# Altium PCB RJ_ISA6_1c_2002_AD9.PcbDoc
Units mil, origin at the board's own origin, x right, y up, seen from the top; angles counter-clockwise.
Board outline 1897.64 x 578.74 mil, 2 copper layers (TOP, Bottom); 8 components, 8 nets, 22 pads, 1 vias.
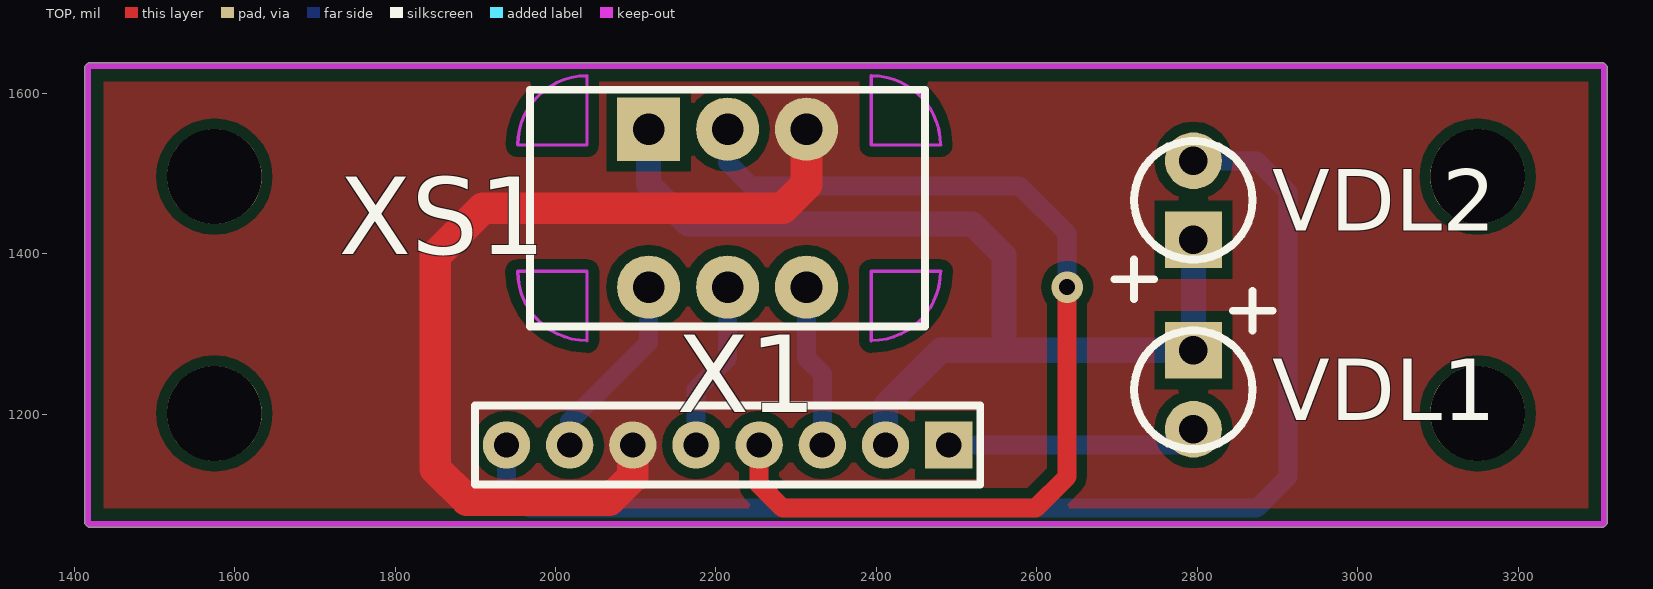
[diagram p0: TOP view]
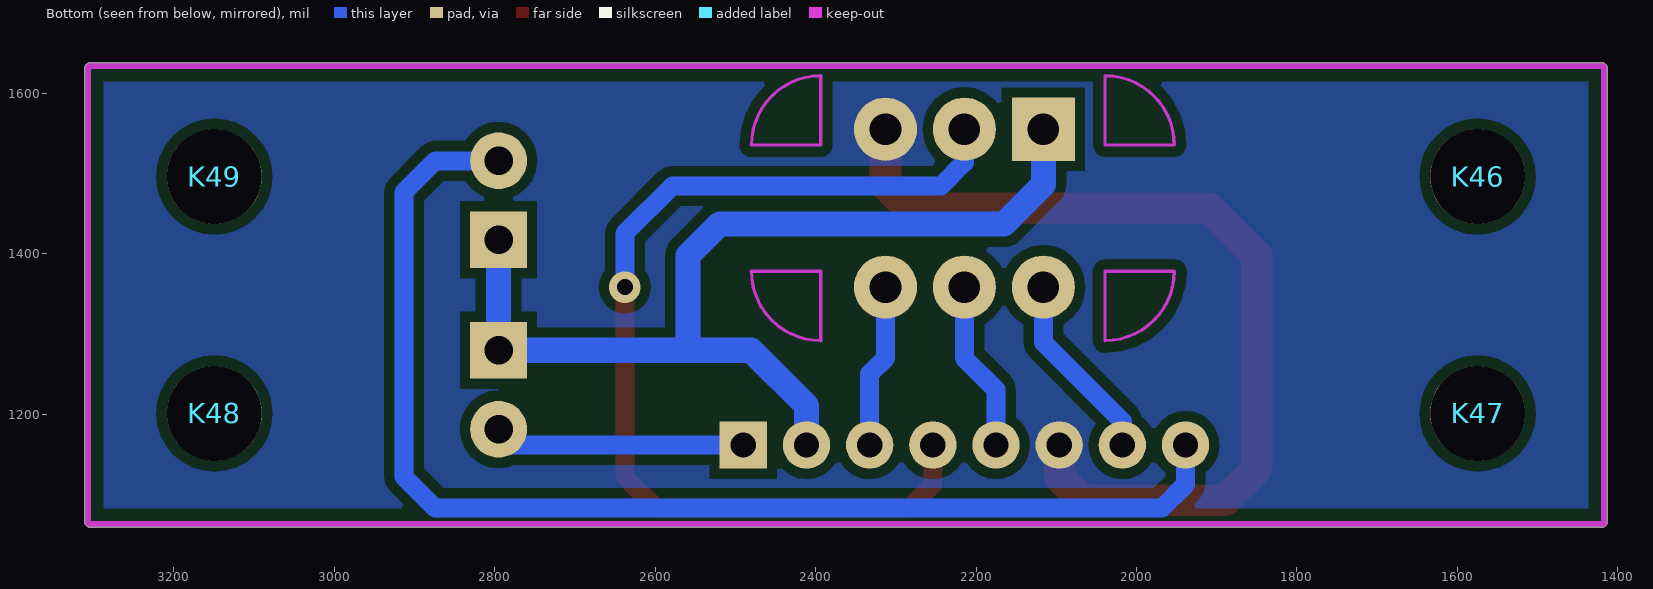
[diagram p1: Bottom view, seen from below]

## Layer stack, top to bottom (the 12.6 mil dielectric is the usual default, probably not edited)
TOP: signal copper 1.4
Dielectric: dielectric 12.6, FR-4, Dk 4.8
Bottom: signal copper 1.4

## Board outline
1413.39,1062.99 1417.32,1059.06 3307.09,1059.06 3311.02,1062.99 3311.02,1633.86 3307.09,1637.8 1417.32,1637.8 1413.39,1633.86

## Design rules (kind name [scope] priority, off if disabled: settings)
Clearance Clearance_TOP_PadToPad [ExistsOnLayer('TOP') And IsPad vs ExistsOnLayer('TOP') And IsPad] p1: gap=15.75
Clearance Clearance_TOP_PadToLine [ExistsOnLayer('TOP') And IsPad vs ExistsOnLayer('TOP') And IsWire] p2: gap=13
Clearance Clearance_TOP_LineToLine [ExistsOnLayer('TOP') And IsWire vs ExistsOnLayer('TOP') And IsWire] p3: gap=13
Clearance Clearance_TOP_ViaToPad [ExistsOnLayer('TOP') And IsVia vs ExistsOnLayer('TOP') And IsPad] p4: gap=15.75
Clearance Clearance_TOP_ViaToLine [ExistsOnLayer('TOP') And IsVia vs ExistsOnLayer('TOP') And IsWire] p5: gap=13
Clearance Clearance_TOP_ViaToVia [ExistsOnLayer('TOP') And IsVia vs ExistsOnLayer('TOP') And IsVia] p6: gap=15.75
Clearance Clearance_Bottom_PadToPad [ExistsOnLayer('Bottom') And IsPad vs ExistsOnLayer('Bottom') And IsPad] p7: gap=15.75
Clearance Clearance_Bottom_PadToLine [ExistsOnLayer('Bottom') And IsPad vs ExistsOnLayer('Bottom') And IsWire] p8: gap=13
Clearance Clearance_Bottom_LineToLine [ExistsOnLayer('Bottom') And IsWire vs ExistsOnLayer('Bottom') And IsWire] p9: gap=13
Clearance Clearance_Bottom_ViaToPad [ExistsOnLayer('Bottom') And IsVia vs ExistsOnLayer('Bottom') And IsPad] p10: gap=15.75
Clearance Clearance_Bottom_ViaToLine [ExistsOnLayer('Bottom') And IsVia vs ExistsOnLayer('Bottom') And IsWire] p11: gap=13
Clearance Clearance_Bottom_ViaToVia [ExistsOnLayer('Bottom') And IsVia vs ExistsOnLayer('Bottom') And IsVia] p12: gap=15.75
Clearance [All] p13: gap=13
PlaneClearance [All] p1: clearance=10
PolygonConnect PolygonConnect_4 [IsPolygon And InNet('GND') And OnLayer('Bottom') vs IsVia] p1: connectstyle=Direct reliefconductorwidth=0 reliefentries=4 polygonreliefangle="90 Angle"
PolygonConnect PolygonConnect_3 [IsPolygon And InNet('GND') And OnLayer('Bottom') vs IsPad] p2: connectstyle=Direct reliefconductorwidth=0 reliefentries=4 polygonreliefangle="90 Angle"
PolygonConnect PolygonConnect_2 [IsPolygon And InNet('GND') And OnLayer('TOP') vs IsVia] p3: connectstyle=Direct reliefconductorwidth=0 reliefentries=4 polygonreliefangle="90 Angle"
PolygonConnect PolygonConnect_1 [IsPolygon And InNet('GND') And OnLayer('TOP') vs IsPad] p4: connectstyle=Direct reliefconductorwidth=0 reliefentries=4 polygonreliefangle="90 Angle"
PolygonConnect [All] p5: connectstyle=Relief reliefconductorwidth=10 reliefentries=4 polygonreliefangle="90 Angle"
RoutingVias [All] p1: holewidth=28 width=50 viastyle="Through Hole" minholewidth=28 minwidth=50 maxholewidth=28 maxwidth=50
SilkscreenOverComponentPads [All] p1: minsilkscreentomaskgap=10
SolderMaskExpansion [All] p1: expansion=4
TestPointUsage [All] p1: valid=0 allowmultiple=FALSE
Testpoint [All] p1: side=15 testpointundercomponent=TRUE minsize=40 maxsize=100 preferedsize=60 minholesize=0 maxholesize=40 preferedholesize=32 testpointgrid=1 style=1023 order=0123456789
Width [All] p1: maxlimit=10 minlimit=10 preferedwidth=10
22 further rules are at their usual default settings.

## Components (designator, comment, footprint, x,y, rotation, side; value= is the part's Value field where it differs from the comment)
K46 "" PIN 1574.8,1496.06 r180 bottom
K47 "" PIN 1574.8,1200.79 r180 bottom
K48 "" PIN 3149.61,1200.79 r180 bottom
K49 "" PIN 3149.61,1496.06 r180 bottom
VDL1 "" VDL-3 2795.28,1279.53 r0 top
VDL2 "" VDL-3 2795.28,1417.32 r180 top
X1 "" WF8_2 2490.16,1161.42 r0 top
XS1 "" CART_6 2214.57,1456.69 r0 top

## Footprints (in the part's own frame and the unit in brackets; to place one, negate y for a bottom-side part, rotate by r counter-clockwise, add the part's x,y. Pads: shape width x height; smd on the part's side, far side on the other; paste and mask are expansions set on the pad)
CART_6 [mm]
  rect 2x2 hole 1: 1(-2.5,2.5)
  round 2 hole 1: 2(-2.5,-2.5) 3(0,2.5) 4(0,-2.5) 5(2.5,2.5) 6(2.5,-2.5)
  silkscreen extent -6.25,-3.75 6.25,3.75
PIN [mm]
  round 3 hole 3: 1(0,0)
VDL-3 [mm]
  rect 1.8x1.8 hole 0.9: 1(0,0)
  round 1.8 hole 0.9: 2(0,-2.5)
  silkscreen extent -1.88,-3.12 2.5,1.88
WF8_2 [mm]
  rect 1.5x1.5 hole 0.8: 1(0,0)
  round 1.5 hole 0.8: 2(-2,0) 3(-4,0) 4(-6,0) 5(-8,0) 6(-10,0) 7(-12,0) 8(-14,0)
  silkscreen extent -15,-1.25 1,1.25

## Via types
v1: diameter 39.37, hole 19.68, TOP to Bottom, 1 vias

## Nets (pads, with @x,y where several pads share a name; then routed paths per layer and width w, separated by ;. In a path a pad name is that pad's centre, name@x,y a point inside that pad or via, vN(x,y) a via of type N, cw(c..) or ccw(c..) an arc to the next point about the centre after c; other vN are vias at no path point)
+3V3: VDL1.1 VDL2.1 X1.2 XS1.1 | length 1266
  Bottom w31.5: XS1.1 2116.14,1486.22 2165.35,1437.01 2519.68,1437.01 2559.05,1397.64 2559.05,1279.53 ; X1.2 2411.42,1210.63 2480.32,1279.53 2559.05,1279.53 ; VDL2.1 VDL1.1 2559.05,1279.53
CS: X1.3 XS1.6 | length 205
  Bottom w23.62: XS1.6 2312.99,1269.68 2332.68,1250 X1.3
DTR2: VDL2.2 X1.8 | length 1540.9
  Bottom w23.62: X1.8 1938.98,1112.2 1968.5,1082.68 2874.02,1082.68 2913.39,1122.05 2913.39,1476.38 2874.02,1515.75 VDL2.2
GND: X1.6 XS1.5 | length 1147.9
  TOP w39.37: X1.6 2096.46,1122.05 2066.93,1092.52 1889.76,1092.52 1850.39,1131.89 1850.39,1397.64 1909.45,1456.69 2283.47,1456.69 2312.99,1486.22 XS1.5
MISO: X1.7 XS1.2 | length 237.6
  Bottom w23.62: X1.7 2017.72,1190.94 2116.14,1289.37 XS1.2
MOSI: X1.5 XS1.4 | length 213.2
  Bottom w23.62: X1.5 2175.2,1230.32 2214.57,1269.68 XS1.4
RTS2: VDL1.2 X1.1 | length 313.3
  Bottom w23.62: X1.1 2775.59,1161.42 VDL1.2
SCK: X1.4 XS1.3 | length 1266
  TOP w23.62: X1.4 2253.94,1112.2 2283.47,1082.68 2598.43,1082.68 2637.8,1122.05 v1(2637.8,1358.27)
  Bottom w23.62: XS1.3 2214.57,1513.78 2244.09,1484.25 2578.74,1484.25 2637.8,1425.2 v1(2637.8,1358.27)
pads on no net: K46.1 K47.1 K48.1 K49.1

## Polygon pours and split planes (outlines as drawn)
GND on TOP "TOP-GND" (solid, remove dead copper, pour order 1000): 1437.01,1614.17 1437.01,1082.68 3287.4,1082.68 3287.4,1614.17 1437.01,1614.17 0,0
GND on Bottom "Bottom-GND" (solid, remove dead copper, pour order 1001): 1437.01,1614.17 1437.01,1082.68 3287.4,1082.68 3287.4,1614.17 1437.01,1614.17 0,0

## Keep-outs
Board:
  lines w3.94: 1952.76,1377.95 2039.37,1377.95 2039.37,1291.34 ; 1952.76,1535.43 2039.37,1535.43 2039.37,1622.05 ; 1953.02,1377.95 ccw(c2039.37,1377.95) 2039.37,1291.61 ; 1953.02,1535.43 cw(c2039.37,1535.43) 2039.37,1621.78 ; 2393.7,1291.34 2393.7,1377.95 2480.32,1377.95 ; 2393.7,1291.61 ccw(c2393.7,1377.95) 2480.05,1377.95 ; 2393.7,1621.78 cw(c2393.7,1535.43) 2480.05,1535.43 ; 2393.7,1622.05 2393.7,1535.43 2480.32,1535.43
  lines w7.87: 1417.32,1062.99 3307.09,1062.99 3307.09,1633.86 1417.32,1633.86 1417.32,1062.99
